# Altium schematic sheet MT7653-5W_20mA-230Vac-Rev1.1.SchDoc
size A4; PageSetup: Record=PageOptions¦CenterHorizontal=True¦CenterVertical=True¦PrintScale=0.97¦XCorrection=1.00¦YCorrection=1.00¦PrintKind=0¦BorderSize=5000000¦LeftOffset=0¦BottomOffset=0¦Orientation=2¦PaperLength=1000¦PaperWidth=1000¦Scale=100¦PaperSource=7¦PrintQuality=-4¦MediaType=1¦DitherType=10¦PrintScaleMode=1¦PaperKind=A4¦PaperIndex=9
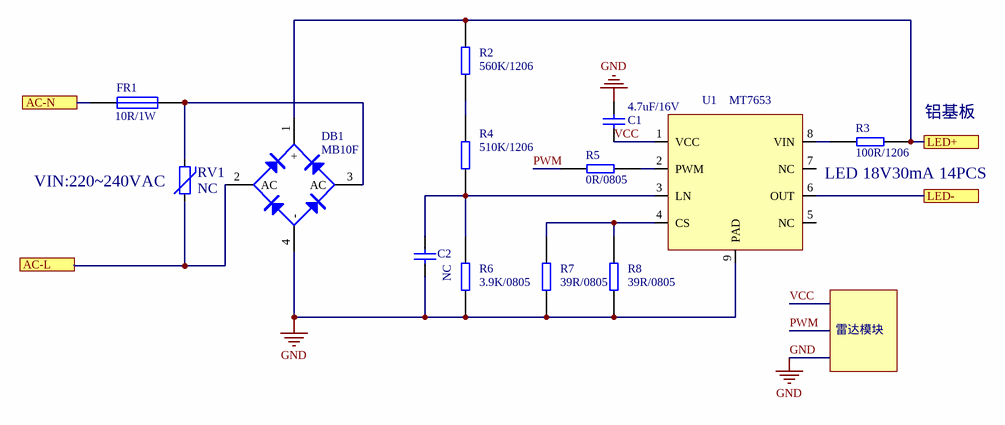
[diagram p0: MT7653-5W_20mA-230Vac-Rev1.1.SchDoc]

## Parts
C1  4.7uF/16V  [R/C/L_1206]
C2  NC  [R/C/L_1206]
DB1  MB10F  [MBS]
FR1  10R/1W  [PIN-W2/E2.8]
R2  560K/1206  [0805]
R3  100R/1206  [0805]
R4  510K/1206  [0805]
R5  0R/0805  [0805]
R6  3.9K/0805  [0805]
R7  39R/0805  [0805]
R8  39R/0805  [0805]
RV1  NC  [PTC7.5-10X5]
U1  MT7653  [SOP8_N 3D]

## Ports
AC-L, AC-N, LED+, LED-

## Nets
GND: C1.1 C2.2 DB1.4(-) R6.1 R7.1 R8.1 U1.9(PAD)
AC-L: DB1.2(AC) RV1.1 ; port AC-L
AC-N: FR1.2 ; port AC-N
LED+: DB1.1(+) R2.2 R3.1 ; port LED+
LED-: U1.6(OUT) ; port LED-
PWM: R5.2
VCC: C1.2 U1.1(VCC)
NetC2_1: C2.1 R4.1 R6.2 U1.3(LN)
NetDB1_3: DB1.3(AC) FR1.1 RV1.2
NetR2_1: R2.1 R4.2
NetR3_2: R3.2 U1.8(VIN)
NetR5_1: R5.1 U1.2(PWM)
NetR7_2: R7.2 R8.2 U1.4(CS)

Not connected (* = marked no-connect by the designer): U1 5(NC) 7(NC)

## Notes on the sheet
- (near R3) 铝基板
- (near RV1) VIN:220|40VAC
- LED 18V30mA 14PCS
- 雷达模块

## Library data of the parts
C1 C2 = CAP_SMD_1206
DB1 = BRIDGE
FR1 = FUSE
R2-R8 = RES1
RV1 = VARISTOR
